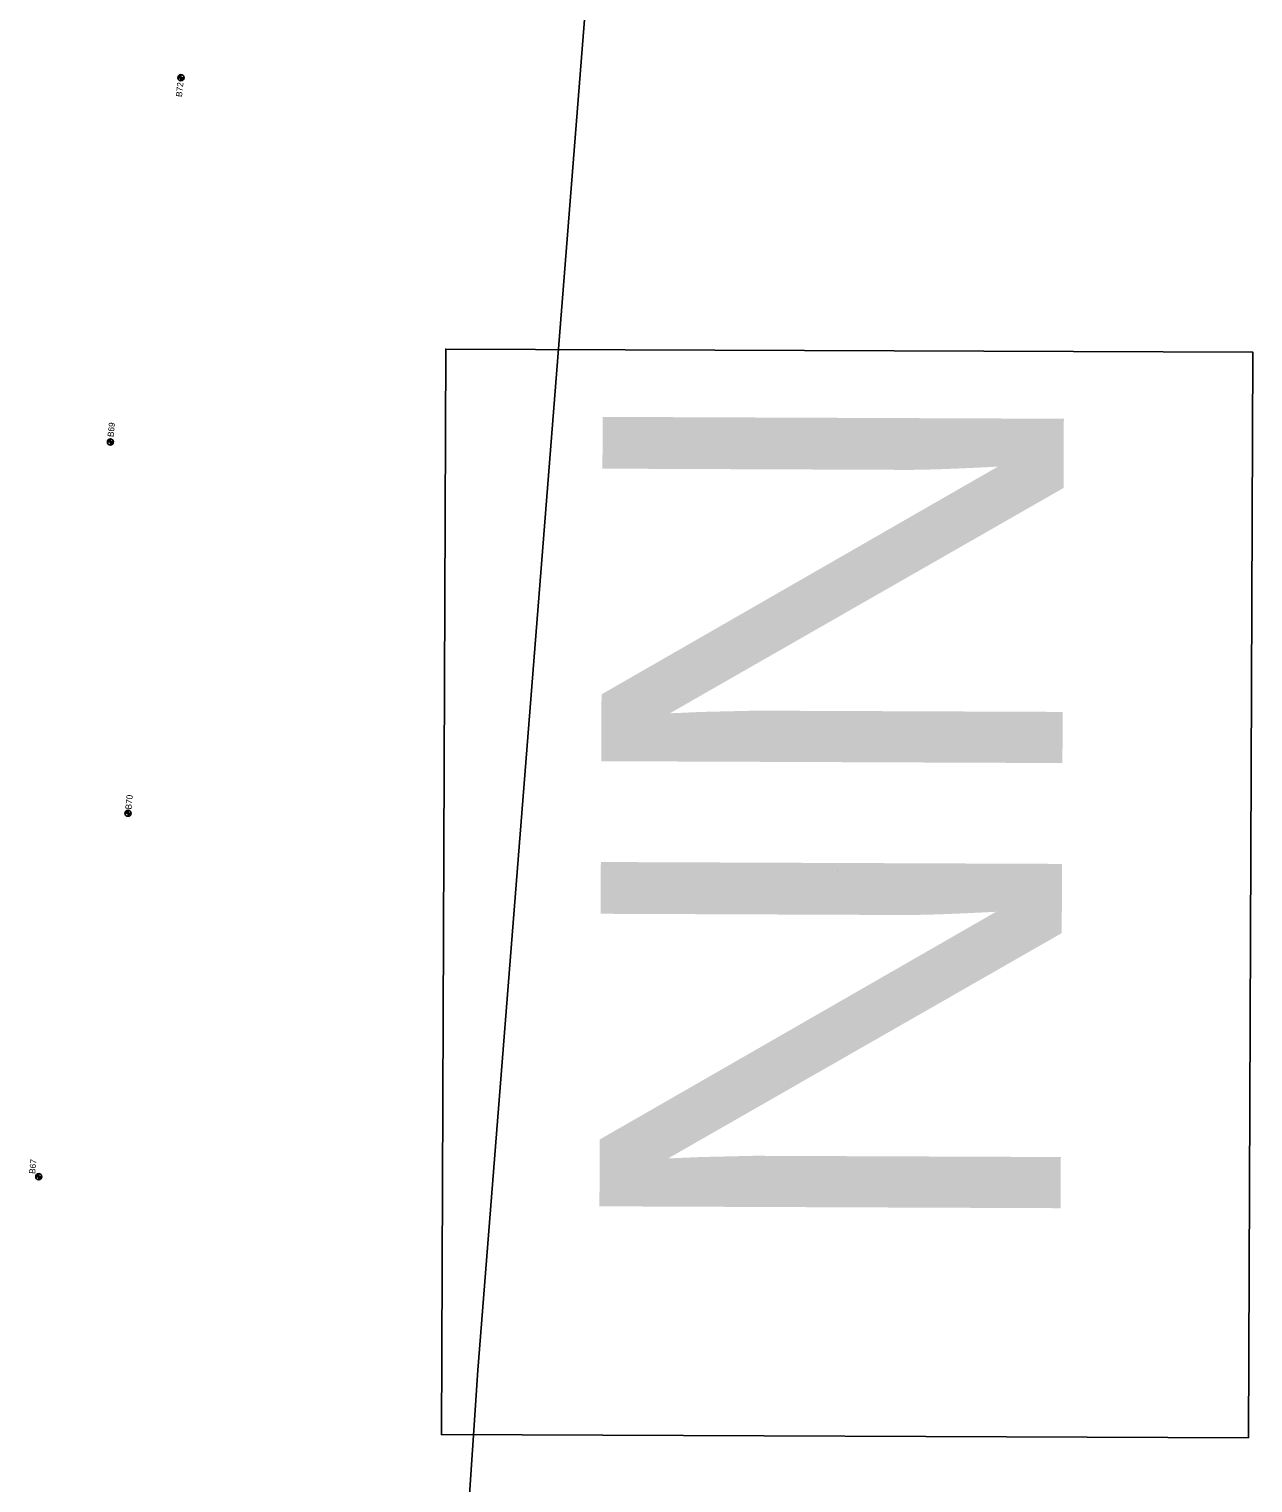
# Model space of a CAD drawing. Extents: x 311409 to 379449, y 121539 to 224848.
# Drawn here: x 359505 to 361495, y 167163 to 169529 of the extents above; entities that cross this region are included whole.
import ezdxf

# ---------------------------------------------------------------- set-up
doc = ezdxf.new("R2010")
doc.units = 0
for name, color, linetype in [('CA-TEXT', 7, 'Continuous'), ('E_SOIL_BORE1 [KAPUR_CADDS_LEVELS]', 7, 'Continuous'), ('E_SOIL_BORE2 [KAPUR_CADDS_LEVELS]', 7, 'Continuous'), ('P_MARK', 7, 'Continuous'), ('P_TC', 7, 'Continuous')]:
    doc.layers.add(name, color=color, linetype=linetype)

msp = doc.modelspace()

# ---------------------------------------------------------------- linework, layer by layer
at = {"layer": 'CA-TEXT'}
msp.add_line((360818.4, 168159.4), (360818.4, 168159.4), dxfattribs=at)
msp.add_lwpolyline([(361487.5, 167236.4), (360175.1, 167241.8), (360182.2, 169008), (361494.7, 169002.7)], close=True, dxfattribs=at)
at = {"layer": 'P_MARK'}
for p, q in [((359746.5, 169449.5), (359756.5, 169449.5)), ((359751.5, 169454.5), (359751.5, 169444.5)), ((359631.8, 168856.8), (359641.8, 168856.8)), ((359636.8, 168861.8), (359636.8, 168851.8)), ((359660.4, 168252.8), (359670.4, 168252.8)), ((359665.4, 168257.8), (359665.4, 168247.8)), ((359515.3, 167661.3), (359525.3, 167661.3)), ((359520.3, 167666.3), (359520.3, 167656.3))]:
    msp.add_line(p, q, dxfattribs=at)
for centre in [(359751.5, 169449.5), (359636.8, 168856.8), (359665.4, 168252.8), (359520.3, 167661.3)]:
    msp.add_circle(centre, 5, dxfattribs=at)
for centre, radius, start, end in [((359751.5, 169449.5), 4.5, 89.9869, 179.9869), ((359751.5, 169449.5), 4, 89.9869, 179.9869), ((359751.5, 169449.5), 3.5, 89.9869, 179.9869), ((359751.5, 169449.5), 3, 89.9869, 179.9869), ((359751.5, 169449.5), 2.5, 89.9869, 179.9869), ((359751.5, 169449.5), 2, 89.9869, 179.9869), ((359751.5, 169449.5), 1.5, 89.9869, 179.9869), ((359751.5, 169449.5), 1, 89.9869, 179.9869), ((359751.5, 169449.5), 0.5, 89.9869, 179.9869), ((359751.5, 169449.5), 4.5, 269.9869, 359.9869), ((359751.5, 169449.5), 4, 269.9869, 359.9869), ((359751.5, 169449.5), 3.5, 269.9869, 359.9869), ((359751.5, 169449.5), 3, 269.9869, 359.9869), ((359751.5, 169449.5), 2.5, 269.9869, 359.9869), ((359751.5, 169449.5), 2, 269.9869, 359.9869), ((359751.5, 169449.5), 1.5, 269.9869, 359.9869), ((359751.5, 169449.5), 1, 269.9869, 359.9869), ((359751.5, 169449.5), 0.5, 269.9869, 359.9869), ((359636.8, 168856.8), 4.5, 89.9869, 179.9869), ((359636.8, 168856.8), 4, 89.9869, 179.9869), ((359636.8, 168856.8), 3.5, 89.9869, 179.9869), ((359636.8, 168856.8), 3, 89.9869, 179.9869), ((359636.8, 168856.8), 2.5, 89.9869, 179.9869), ((359636.8, 168856.8), 2, 89.9869, 179.9869), ((359636.8, 168856.8), 1.5, 89.9869, 179.9869), ((359636.8, 168856.8), 1, 89.9869, 179.9869), ((359636.8, 168856.8), 0.5, 89.9869, 179.9869), ((359636.8, 168856.8), 4.5, 269.9869, 359.9869), ((359636.8, 168856.8), 4, 269.9869, 359.9869), ((359636.8, 168856.8), 3.5, 269.9869, 359.9869), ((359636.8, 168856.8), 3, 269.9869, 359.9869), ((359636.8, 168856.8), 2.5, 269.9869, 359.9869), ((359636.8, 168856.8), 2, 269.9869, 359.9869), ((359636.8, 168856.8), 1.5, 269.9869, 359.9869), ((359636.8, 168856.8), 1, 269.9869, 359.9869), ((359636.8, 168856.8), 0.5, 269.9869, 359.9869), ((359665.4, 168252.8), 4.5, 89.9869, 179.9869), ((359665.4, 168252.8), 4, 89.9869, 179.9869), ((359665.4, 168252.8), 3.5, 89.9869, 179.9869), ((359665.4, 168252.8), 3, 89.9869, 179.9869), ((359665.4, 168252.8), 2.5, 89.9869, 179.9869), ((359665.4, 168252.8), 2, 89.9869, 179.9869), ((359665.4, 168252.8), 1.5, 89.9869, 179.9869), ((359665.4, 168252.8), 1, 89.9869, 179.9869), ((359665.4, 168252.8), 0.5, 89.9869, 179.9869), ((359665.4, 168252.8), 4.5, 269.9869, 359.9869), ((359665.4, 168252.8), 4, 269.9869, 359.9869), ((359665.4, 168252.8), 3.5, 269.9869, 359.9869), ((359665.4, 168252.8), 3, 269.9869, 359.9869), ((359665.4, 168252.8), 2.5, 269.9869, 359.9869), ((359665.4, 168252.8), 2, 269.9869, 359.9869), ((359665.4, 168252.8), 1.5, 269.9869, 359.9869), ((359665.4, 168252.8), 1, 269.9869, 359.9869), ((359665.4, 168252.8), 0.5, 269.9869, 359.9869), ((359520.3, 167661.3), 4.5, 89.9869, 179.9869), ((359520.3, 167661.3), 4, 89.9869, 179.9869), ((359520.3, 167661.3), 3.5, 89.9869, 179.9869), ((359520.3, 167661.3), 3, 89.9869, 179.9869), ((359520.3, 167661.3), 2.5, 89.9869, 179.9869), ((359520.3, 167661.3), 2, 89.9869, 179.9869), ((359520.3, 167661.3), 1.5, 89.9869, 179.9869), ((359520.3, 167661.3), 1, 89.9869, 179.9869), ((359520.3, 167661.3), 0.5, 89.9869, 179.9869), ((359520.3, 167661.3), 4.5, 269.9869, 359.9869), ((359520.3, 167661.3), 4, 269.9869, 359.9869), ((359520.3, 167661.3), 3.5, 269.9869, 359.9869), ((359520.3, 167661.3), 3, 269.9869, 359.9869), ((359520.3, 167661.3), 2.5, 269.9869, 359.9869), ((359520.3, 167661.3), 2, 269.9869, 359.9869), ((359520.3, 167661.3), 1.5, 269.9869, 359.9869), ((359520.3, 167661.3), 1, 269.9869, 359.9869), ((359520.3, 167661.3), 0.5, 269.9869, 359.9869)]:
    msp.add_arc(centre, radius, start, end, dxfattribs=at)
at = {"layer": 'P_TC'}
msp.add_lwpolyline([(360355.1, 163291.2), (360178.1, 164047.2), (360111.7, 164403), (360098.2, 164475), (360067.6, 164852.2), (360112, 165511.8), (360234.3, 167346.5), (360439.2, 169942.6), (360458.8, 170191.1), (360539.2, 171209.4)], dxfattribs=at)

# ---------------------------------------------------------------- texts
at = {"layer": 'CA-TEXT'}
msp.add_text('NN', height=750, rotation=89.767, dxfattribs=at).set_placement((361181.7, 167527.8))
at = {"layer": 'E_SOIL_BORE1 [KAPUR_CADDS_LEVELS]'}
for s, p in [('B70', (359670.8, 168258.5)), ('B67', (359514.4, 167665.5))]:
    msp.add_text(s, height=10, rotation=84.1728, dxfattribs=at).set_placement(p)
at = {"layer": 'E_SOIL_BORE2 [KAPUR_CADDS_LEVELS]'}
for s, p in [('B72', (359753.1, 169417.7)), ('B69', (359641.9, 168864.4))]:
    msp.add_text(s, height=10, rotation=84.1728, dxfattribs=at).set_placement(p)

doc.saveas('drawing.dxf')
